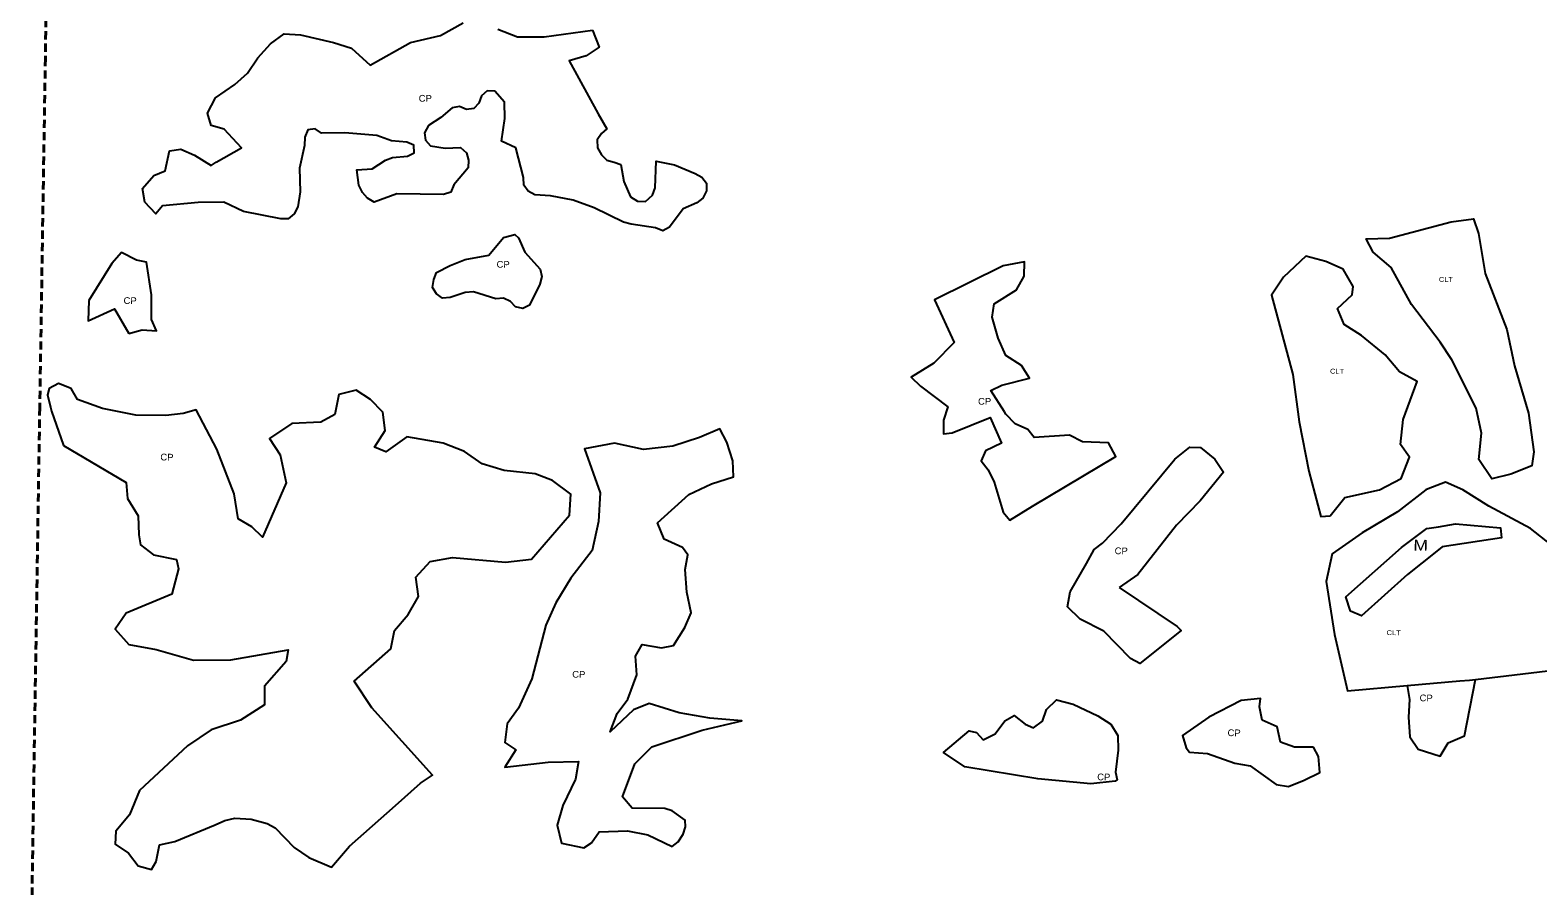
# Model space of a CAD drawing. Extents: x 713589 to 726391, y 7177764 to 7191819.
# Drawn here: x 713646 to 715078, y 7181659 to 7182472 of the extents above; entities that cross this region are included whole.
import ezdxf
from ezdxf.enums import TextEntityAlignment as Align

# ---------------------------------------------------------------- set-up
doc = ezdxf.new("R2010")
doc.units = 0
doc.header["$LTSCALE"] = 2.6
doc.linetypes.add('MEDIUM_DASHED', pattern=[4.5, 3, -1.5])
doc.layers.add('63', color=7, linetype='Continuous', lineweight=25)

msp = doc.modelspace()

# ---------------------------------------------------------------- linework, layer by layer
at = {"layer": '63', "linetype": 'MEDIUM_DASHED', "lineweight": 40}
msp.add_lwpolyline([(713662.75, 7182590.64), (713662.34, 7182564.58), (713660.44, 7182445.55), (713655.15, 7182114.03), (713647.81, 7181654.67), (713646.02, 7181542.38)], dxfattribs=at)
at = {"layer": '63'}
for points in [[(714181.87, 7182303.36), (714161.66, 7182310.68), (714140.13, 7182314.7), (714125.21, 7182315.71), (714118.92, 7182319.04), (714114.96, 7182325.01), (714114.64, 7182332.3), (714107.39, 7182360.48), (714093.82, 7182366.8), (714096.83, 7182388.34), (714096.53, 7182403.59), (714087.27, 7182414.21), (714079.97, 7182414.55), (714074.66, 7182409.59), (714072.33, 7182402.63), (714067.35, 7182397.67), (714060.39, 7182396.69), (714053.77, 7182399.68), (714046.81, 7182398.37), (714036.19, 7182389.1), (714024.24, 7182381.5), (714020.59, 7182374.55), (714021.57, 7182367.59), (714026.2, 7182362.28), (714040.11, 7182359.93), (714054.7, 7182360.57), (714060.32, 7182355.59), (714062.3, 7182348.63), (714061.96, 7182341.34), (714048.34, 7182325.12), (714045.68, 7182318.17), (714038.72, 7182315.86), (713994.31, 7182316.59), (713972.75, 7182308.68), (713966.46, 7182312.66), (713961.83, 7182317.97), (713958.2, 7182324.94), (713956.23, 7182339.52), (713970.82, 7182340.49), (713983.42, 7182348.76), (713990.06, 7182351.07), (714004.31, 7182352.37), (714010.61, 7182355.67), (714010.29, 7182362.97), (714003.67, 7182365.63), (713989.09, 7182366.98), (713975.18, 7182371.97), (713945.02, 7182374.67), (713922.82, 7182374.38), (713916.86, 7182378.37), (713909.9, 7182377.38), (713906.9, 7182370.43), (713906.56, 7182362.47), (713901.88, 7182340.94), (713902.51, 7182318.4), (713900.17, 7182304.16), (713896.84, 7182297.53), (713891.2, 7182292.9), (713884.02, 7182293.05), (713848.59, 7182299.73), (713830.05, 7182308.71), (713805.52, 7182308.42), (713771.66, 7182305.16), (713765.41, 7182297.77), (713755.02, 7182308.71), (713752.72, 7182321.63), (713763.34, 7182334.21), (713774.29, 7182338.5), (713778.3, 7182357.38), (713789.23, 7182359.02), (713802.15, 7182353.37), (713817.96, 7182343.45), (713822.66, 7182346.78), (713846.78, 7182360.22), (713830.36, 7182378.18), (713818.1, 7182381.51), (713814.48, 7182393.12), (713822.12, 7182407.69), (713840.37, 7182420.58), (713852.32, 7182431.17), (713862.29, 7182445.73), (713874.24, 7182458.97), (713887.18, 7182468.56), (713902.76, 7182467.54), (713934.23, 7182460.53), (713951.12, 7182454.86), (713968.99, 7182438.93), (714007.14, 7182460.41), (714035.65, 7182466.99), (714057.21, 7182479.21)], [(714090.35, 7182473.19), (714108.89, 7182465.87), (714134.08, 7182465.83), (714180.16, 7182472.05)], [(714180.16, 7182472.05), (714186.43, 7182455.8), (714174.15, 7182447.87), (714157.9, 7182442.92), (714185.66, 7182392.7), (714193.65, 7182378.23), (714188.61, 7182373.94), (714184.62, 7182367.98), (714184.94, 7182360.36), (714188.58, 7182353.72), (714193.87, 7182348.74), (714200.65, 7182346.64), (714207.15, 7182344.63), (714209.84, 7182328.31), (714216.38, 7182313.95), (714222.84, 7182309.63), (714230.58, 7182309.37), (714237.2, 7182315.48), (714239.71, 7182322.43), (714240.49, 7182347.74), (714258.16, 7182344.33), (714277.7, 7182336.01), (714283.99, 7182332.35), (714288.29, 7182326.71), (714288.28, 7182319.42), (714284.95, 7182312.47), (714279.31, 7182308.17), (714266.37, 7182302.55), (714253.42, 7182285.01), (714246.79, 7182281.38), (714239.83, 7182284.37), (714216.97, 7182287.72), (714209.68, 7182289.72), (714181.87, 7182303.36)], [(715018.75, 7181855.45), (715116.49, 7181867.04), (715099.62, 7181950.87), (715090.4, 7181983.7), (715071.2, 7181998.64), (715031.47, 7182019.92), (715006.64, 7182035.54), (714990.41, 7182042.85), (714973.81, 7182036.47), (714971.51, 7182035.59), (714944.63, 7182014.76), (714911.12, 7181994.6), (714882.59, 7181974.76), (714876.91, 7181948.59), (714884.78, 7181898.2), (714897.28, 7181844.51), (714953.97, 7181849.54)], [(714953.97, 7181849.54), (714956.13, 7181836.37), (714955.11, 7181819.47), (714956.4, 7181800.91), (714964.34, 7181789.3), (714985.21, 7181782.64), (714992.85, 7181795.22), (715008.44, 7181801.82), (715018.75, 7181855.45)], [(714953.97, 7181849.54), (715003.8, 7181853.96), (715013.18, 7181854.79), (715018.75, 7181855.45)]]:
    msp.add_lwpolyline(points, dxfattribs=at)
for points in [[(715052.4, 7182050.37), (715034.16, 7182046.09), (715021.93, 7182064.34), (715024.62, 7182089.19), (715019.36, 7182113.06), (714996.24, 7182158.84), (714985.33, 7182175.76), (714957.88, 7182211.6), (714938.72, 7182246.76), (714921.51, 7182261.37), (714914.91, 7182273.99), (714937.11, 7182274.6), (714995.79, 7182290.08), (715017.01, 7182293.03), (715021.62, 7182279.1), (715027.86, 7182240.98), (715048.65, 7182187.92), (715055.88, 7182153.44), (715069.06, 7182108.34), (715074.31, 7182071.55), (715072.3, 7182058.29)], [(714067.06, 7182223.68), (714059.11, 7182223.03), (714044.85, 7182218.08), (714037.56, 7182217.43), (714031.93, 7182221.75), (714028.3, 7182227.72), (714029.3, 7182235.34), (714031.97, 7182241.96), (714044.9, 7182248.57), (714059.16, 7182254.18), (714081.7, 7182258.45), (714095.65, 7182275.33), (714106.38, 7182277.89), (714109.9, 7182274.98), (714115.84, 7182261.38), (714130.4, 7182245.11), (714132.05, 7182238.15), (714130.05, 7182230.86), (714120.4, 7182211), (714114.1, 7182207.69), (714107.14, 7182209.36), (714102.18, 7182214.34), (714095.56, 7182217.67), (714088.26, 7182217.01)], [(713739.76, 7182184.05), (713752.36, 7182187.35), (713765.9, 7182186.45), (713761.28, 7182197.39), (713761.32, 7182220.64), (713756.55, 7182251.65), (713747.17, 7182253.64), (713732.93, 7182260.95), (713723.63, 7182250.36), (713701.7, 7182215.27), (713701.01, 7182196.05), (713726.21, 7182207.27)], [(714633.22, 7182087.52), (714599.75, 7182085.26), (714593.46, 7182092.89), (714581.54, 7182098.21), (714572.61, 7182107.51), (714571.33, 7182109.51), (714558.39, 7182129.74), (714569.01, 7182135.02), (714595.2, 7182141.61), (714587.6, 7182153.55), (714572.7, 7182163.19), (714565.44, 7182179.44), (714559.83, 7182199.66), (714561.51, 7182212.25), (714582.75, 7182225.47), (714590.06, 7182238.39), (714590.41, 7182251.97), (714570.19, 7182248.36), (714505.11, 7182216.08), (714523.67, 7182175.58), (714504.42, 7182155.68), (714482.85, 7182142.46), (714491.79, 7182133.82), (714517.6, 7182114.23), (714513.61, 7182101.64), (714513.58, 7182088.72), (714521.87, 7182089.7), (714557.9, 7182104.13), (714568.64, 7182079.99), (714553.33, 7182072.41), (714549.33, 7182063.14), (714555.95, 7182054.51), (714561.56, 7182042.9), (714570.13, 7182014.39), (714576.42, 7182006.75), (714598.15, 7182019.91), (714677.27, 7182067.23), (714670.33, 7182080.17), (714645.47, 7182081.21)], [(714880.66, 7182010.89), (714894.61, 7182028.1), (714927.76, 7182035.67), (714948.33, 7182046.24), (714955.98, 7182066.44), (714947.72, 7182078.72), (714950.08, 7182102.24), (714963.39, 7182138.34), (714946.51, 7182147.65), (714932.95, 7182163.58), (714910.44, 7182182.18), (714894.22, 7182192.48), (714887.59, 7182207.79), (714901.56, 7182220.64), (714902.56, 7182228.59), (714892.98, 7182245.18), (714876.75, 7182252.49), (714857.54, 7182257.5), (714836.3, 7182237.65), (714825, 7182220.43), (714845.42, 7182145.17), (714851.31, 7182100.09), (714860.51, 7182053.34), (714872.04, 7182010.24)], [(713677.74, 7182077.51), (713737.08, 7182042.63), (713738.41, 7182027.33), (713748.68, 7182010.7), (713749.19, 7181992.88), (713750.83, 7181983.27), (713763.08, 7181973.63), (713784.94, 7181969.29), (713786.92, 7181960.34), (713780.58, 7181936.49), (713737.13, 7181918.33), (713726.84, 7181903.1), (713739.74, 7181888.5), (713765.58, 7181883.82), (713801.02, 7181873.82), (713836.49, 7181874.09), (713891.18, 7181883.61), (713889.18, 7181872.34), (713868.59, 7181849.18), (713868.56, 7181831.28), (713845.67, 7181816.74), (713817.82, 7181807.51), (713795.59, 7181792.3), (713749.78, 7181749.95), (713740.46, 7181726.77), (713727.51, 7181711.21), (713726.83, 7181698.95), (713739.41, 7181690.32), (713748.67, 7181678.37), (713761.26, 7181675.03), (713765.58, 7181682.65), (713768.92, 7181698.22), (713783.5, 7181701.51), (713821.59, 7181717.46), (713830.77, 7181721.3), (713840.34, 7181723.77), (713855.8, 7181722.82), (713871.16, 7181718.46), (713878.89, 7181714.46), (713896.76, 7181695.9), (713910.85, 7181686.2), (713932.26, 7181677.26), (713949.48, 7181697.09), (713992.97, 7181735.72), (714016.69, 7181756.78), (714028.23, 7181764.61), (713970.63, 7181828.61), (713953.74, 7181853.87), (713988.62, 7181884.44), (713991.96, 7181902), (714004.91, 7181917.22), (714014.88, 7181934.11), (714012.26, 7181952.67), (714025.88, 7181967.56), (714047.09, 7181971.17), (714097.46, 7181966.78), (714122.32, 7181969.72), (714158.18, 7182011.42), (714159.54, 7182031.31), (714142, 7182044.26), (714125.77, 7182050.58), (714096.28, 7182053.95), (714075.41, 7182060.28), (714058.53, 7182071.91), (714038.33, 7182079.89), (714003.87, 7182085.92), (713983.96, 7182071.7), (713973.03, 7182076.02), (713983.33, 7182091.91), (713981.04, 7182109.15), (713969.13, 7182121.43), (713955.56, 7182130.07), (713939.31, 7182126.12), (713935.3, 7182106.91), (713922.03, 7182099.64), (713894.52, 7182098.36), (713873.29, 7182084.14), (713883.54, 7182068.88), (713889.13, 7182042.03), (713866.75, 7181990.55), (713856.63, 7182000.22), (713843.57, 7182008.04), (713839.74, 7182031.81), (713823.2, 7182074.03), (713803.68, 7182111.48), (713791.47, 7182108.14), (713774.9, 7182106.18), (713746.4, 7182106.56), (713714.59, 7182112.91), (713691.07, 7182121.23), (713685.13, 7182131.85), (713672.87, 7182136.51), (713663.92, 7182131.88), (713662.58, 7182125.59), (713665.28, 7182114.07), (713666.21, 7182110.11)], [(714099.19, 7181813.34), (714096.84, 7181795.44), (714107.44, 7181788.47), (714096.73, 7181772.24), (714137.98, 7181776.84), (714166.81, 7181777.35), (714164.06, 7181760.87), (714152.09, 7181735.7), (714146.43, 7181717.15), (714150.71, 7181699.91), (714171.91, 7181695.56), (714179.21, 7181700.19), (714186.52, 7181710.79), (714213.36, 7181711.73), (714232.58, 7181707.73), (714255.74, 7181696.73), (714261.64, 7181701.23), (714266.28, 7181708.47), (714268.33, 7181715.55), (714268.06, 7181721.78), (714255.82, 7181730.56), (714248.86, 7181732.89), (714217.71, 7181733.27), (714208.78, 7181743.89), (714220.43, 7181775.35), (714236.36, 7181791.57), (714284.44, 7181807.4), (714321.87, 7181816.21), (714291.54, 7181818.78), (714262.31, 7181823.81), (714234.09, 7181832.49), (714219.13, 7181826.54), (714196.89, 7181805.63), (714203.61, 7181823.11), (714213.57, 7181836.68), (714222.23, 7181859.86), (714220.93, 7181877.43), (714227.24, 7181888.69), (714245.8, 7181885.34), (714257.07, 7181887.64), (714267.7, 7181904.86), (714273.69, 7181918.77), (714269.75, 7181938.33), (714268.13, 7181959.87), (714270.8, 7181973.79), (714265.51, 7181980.76), (714248.29, 7181988.74), (714242.02, 7182004.32), (714271.56, 7182031.12), (714293.12, 7182041.36), (714314.01, 7182047.95), (714313.37, 7182063.2), (714307.76, 7182080.77), (714301.16, 7182093.38), (714281.92, 7182085.12), (714256.39, 7182076.88), (714228.55, 7182073.94), (714201.05, 7182079.95), (714172.54, 7182074.37), (714187.38, 7182032.59), (714185.68, 7182005.41), (714179.67, 7181977.91), (714159.41, 7181951.77), (714145.45, 7181928.26), (714135.81, 7181907.07), (714122.46, 7181856.05), (714109.82, 7181828.23)], [(714680.32, 7181942.68), (714735.53, 7181905.75), (714739.3, 7181901.77), (714700.14, 7181870.67), (714691.2, 7181875.32), (714665.72, 7181901.22), (714643.21, 7181912.52), (714631.3, 7181924.47), (714633.97, 7181938.72), (714649.21, 7181965.65), (714656.65, 7181978.81), (714664.54, 7181984.73), (714682.13, 7182003.26), (714733.27, 7182064.49), (714747.54, 7182076.07), (714757.48, 7182075.72), (714771.38, 7182064.76), (714779.32, 7182052.15), (714757.4, 7182025.01), (714734.82, 7182001.85), (714697.96, 7181955.18)], [(714983.52, 7182000.53), (714999.96, 7182003.07), (715042.7, 7181999.35), (715043.35, 7181990.07), (714987.1, 7181981.43), (714982.06, 7181977.4), (714954.14, 7181955.09), (714910.66, 7181915.72), (714900.06, 7181920.38), (714895.78, 7181933.98), (714948.55, 7181980.62), (714972.44, 7181998.81)], [(714636.78, 7181832), (714659.96, 7181821.02), (714672.54, 7181813.05), (714679.15, 7181802.1), (714679.46, 7181788.18), (714676.77, 7181767.31), (714678.47, 7181759.99), (714676.69, 7181758.66), (714653.55, 7181756.38), (714603.06, 7181761.12), (714533.65, 7181772.53), (714513.45, 7181785.91), (714537.97, 7181806.64), (714544.93, 7181804.97), (714551.22, 7181798), (714562.49, 7181803.62), (714571.79, 7181816.2), (714580.75, 7181821.15), (714591.01, 7181812.85), (714598.96, 7181809.53), (714607.58, 7181815.81), (714611.25, 7181826.74), (714620.87, 7181836)], [(714864.92, 7181791.12), (714847.02, 7181791.15), (714833.44, 7181795.81), (714830.48, 7181810.4), (714816.24, 7181816.72), (714813.61, 7181829.32), (714814.55, 7181837.18), (714796.21, 7181835.55), (714765.61, 7181819.65), (714740.45, 7181802.15), (714743.95, 7181790.33), (714747.26, 7181786.35), (714764.16, 7181784.99), (714790.33, 7181776), (714804.9, 7181773.32), (714829.4, 7181755.72), (714841.33, 7181753.71), (714855.92, 7181759.65), (714870.84, 7181766.92), (714869.54, 7181782.17)]]:
    msp.add_lwpolyline(points, close=True, dxfattribs=at)

# ---------------------------------------------------------------- texts
for s, height, width, p in [('CP', 6.4, 1.05, (714021.27, 7182404.16)), ('CP', 6.4, 1.05, (714095.22, 7182246.45)), ('CLT', 4.64, 1.15, (714990.75, 7182232.94)), ('CP', 6.4, 1.05, (713740.93, 7182212)), ('CLT', 4.64, 1.15, (714887.33, 7182145.82)), ('CP', 6.4, 1.05, (714552.5, 7182116.35)), ('CP', 6.4, 1.05, (713775.87, 7182063.37)), ('CP', 6.4, 1.05, (714682.26, 7181974.35)), ('M', 10.4, 1.2, (714966.66, 7181977.7)), ('CLT', 4.64, 1.15, (714941.04, 7181897.51)), ('CP', 6.4, 1.05, (714167.06, 7181857.07)), ('CP', 6.4, 1.05, (714971.91, 7181834.63)), ('CP', 6.4, 1.05, (714789.5, 7181801.54)), ('CP', 6.4, 1.05, (714665.68, 7181759.59))]:
    msp.add_text(s, height=height, rotation=359.062, dxfattribs=dict(at, width=width)).set_placement(p, align=Align.CENTER)

doc.saveas('drawing.dxf')
